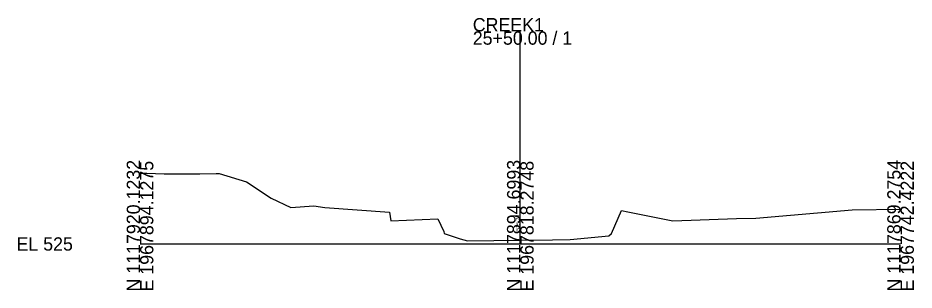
# Model space of a CAD drawing. Extents: x -26 to 163, y -10 to 10052.
# Drawn here: x -25.7 to 162.8, y 4990.3 to 5047.5 of the extents above; entities that cross this region are included whole.
import ezdxf

# ---------------------------------------------------------------- set-up
doc = ezdxf.new("R2010")
doc.units = 0
for name, color, linetype in [('RD_GPK_XS_Cell', 7, 'Continuous'), ('RD_XS_ExGround', 7, 'Continuous'), ('RD_XS_TX_Elev_EX', 7, 'Continuous')]:
    doc.layers.add(name, color=color, linetype=linetype)

msp = doc.modelspace()

# ---------------------------------------------------------------- linework, layer by layer
at = {"layer": 'RD_GPK_XS_Cell'}
for p, q in [((80, 5000), (80, 5044.71)), ((0, 5000), (80, 5000)), ((80, 5000), (160, 5000))]:
    msp.add_line(p, q, dxfattribs=at)
at = {"layer": 'RD_XS_ExGround'}
for p, q in [((0, 5014.9), (1.46, 5014.89)), ((1.46, 5014.89), (5.08, 5014.76)), ((5.08, 5014.76), (12.59, 5014.78)), ((12.59, 5014.78), (15.98, 5014.82)), ((15.98, 5014.82), (16.63, 5014.82)), ((16.63, 5014.82), (22.42, 5013.1)), ((22.42, 5013.1), (27.6, 5009.61)), ((27.6, 5009.61), (31.73, 5007.69)), ((31.73, 5007.69), (36.54, 5008.04)), ((36.54, 5008.04), (38.85, 5007.7)), ((38.85, 5007.7), (52.47, 5006.72)), ((52.47, 5006.72), (52.78, 5004.87)), ((99.17, 5002.23), (101.32, 5007.07)), ((101.32, 5007.07), (102.63, 5006.76)), ((102.63, 5006.76), (112.06, 5004.87)), ((129.53, 5005.41), (149.84, 5007.17)), ((149.84, 5007.17), (160, 5007.32)), ((52.78, 5004.87), (62.64, 5005.26)), ((62.64, 5005.26), (63.91, 5002.65)), ((112.06, 5004.87), (125.5, 5005.38)), ((125.5, 5005.38), (129.53, 5005.41)), ((63.91, 5002.65), (63.97, 5002.18)), ((63.97, 5002.18), (67.37, 5001.06)), ((98.62, 5001.74), (99.17, 5002.23)), ((67.37, 5001.06), (68.92, 5000.63)), ((68.92, 5000.63), (80, 5000.79)), ((80, 5000.79), (86.77, 5000.89)), ((86.77, 5000.89), (90.51, 5000.97)), ((90.51, 5000.97), (98.62, 5001.74))]:
    msp.add_line(p, q, dxfattribs=at)

# ---------------------------------------------------------------- texts
at = {"layer": 'RD_GPK_XS_Cell'}
for s, p in [('CREEK1', (70, 5044.71)), ('25+50.00 / 1', (70, 5041.91)), ('EL 525', (-26, 4998.6))]:
    msp.add_text(s, height=2.8, dxfattribs=at).set_placement(p)
for s, p in [('N 1117920.1232', (0, 4990)), ('E 1967894.1275', (2.8, 4990)), ('N 1117894.6993', (80, 4990)), ('E 1967818.2748', (82.8, 4990)), ('N 1117869.2754', (160, 4990)), ('E 1967742.4222', (162.8, 4990))]:
    msp.add_text(s, height=2.8, rotation=90, dxfattribs=at).set_placement(p)
at = {"layer": 'RD_XS_TX_Elev_EX'}
msp.add_text('525.79', height=0.8, rotation=90, dxfattribs=at).set_placement((79.9, 5002.79))

doc.saveas('drawing.dxf')
